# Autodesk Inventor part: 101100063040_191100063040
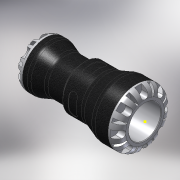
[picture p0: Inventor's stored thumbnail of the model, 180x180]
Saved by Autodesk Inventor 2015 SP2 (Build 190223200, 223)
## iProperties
Created: 2016-12
Part Number: 101100063040_191100063040
Material: PVC-Piping
Description: PLASSON REDUCING COUPLING 63X40 SERIES 1
Document SubType Name: Modeling
Designer: KIM
Mass: 693.001 g
Surface Area: 891.798 cm^2
Volume: 495.001 cm^3
Density: 1.4 g/cm^3
Appearance: Black Cast
Author: KIM
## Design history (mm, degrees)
derived "1011.ipt"
feature "Solid1::1011.ipt"
tag "TaggingFeature1"
body "Solid1"
other parameters: "d0" = 183, "d2" = 38.22, "d3" = 63, "d4" = 103, "d5" = 75.6, "d6" = 91, "d7" = 5.25, "d11" = 29.82, "d12" = 71, "d13" = 3.33333, "d14" = 82.4, "d15" = 56, "d16" = 20 deg, "d17" = 20 deg, "d18" = 130 deg, "d22" = 10.96, "d25" = 10.96, "d26" = 0, "d28" = 360 deg, "d30" = 8 deg, "d31" = 1.26, "d32" = 8 deg, "d33" = 1.26, "d35" = 0, "d37" = 360 deg, "d39" = 8, "d42" = 8, "d43" = 0, "d45" = 360 deg, "d47" = 0.8, "d48" = 8 deg, "d49" = 8 deg, "d50" = 0.8, "d52" = 0, "d54" = 360 deg, "d56" = 14, "d57" = 20.6, "d58" = 0.5, "d60" = 12.36, "d61" = 15.75, "d62" = 17.46, "d63" = 0, "d66" = 0, "d68" = 360 deg, "d75" = 10.01969, "d77" = 80.34, "d78" = 1.03, "d_" = 63, "E_" = 103, "H_" = 183, "l_" = 91, "l1" = 71, "Plasson" = 1, "d21" = 13.7, "d23" = 103, "d24" = 75.6, "d59" = 20.03938
